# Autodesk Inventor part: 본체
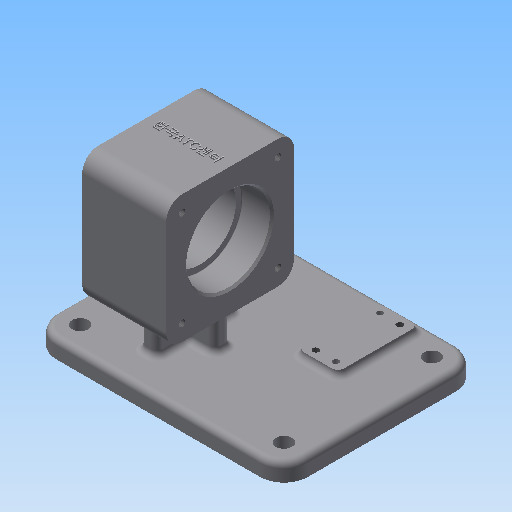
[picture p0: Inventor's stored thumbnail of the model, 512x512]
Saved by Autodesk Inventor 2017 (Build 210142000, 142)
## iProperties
Created: 2019-09
Part Number: 본체
Material: 알루미늄 6061
Document SubType Name: Modeling
Designer: mduedu
Density: 2.71 g/cm^3
Mass: 636.364 g
Surface Area: 520.125 cm^2
Volume: 234.821 cm^3
Appearance: 기본값
Author: mduedu
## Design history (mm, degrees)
sketch "스케치1"
  geometry: L1 (42, -62)-(-84, -62); L2 (-84, -62)-(-84, 36); L3 (-84, 36)-(42, 36); L4 (42, 36)-(42, -62); 1 further point
  constraints: 8 end point, 2 parallel, 1 horizontal, 1 perpendicular
  dimensions: "d0" = 36 distance from line of L3 point (0, 0); "d1" = 98 distance of L1.end L2.end; "d2" = 42 distance from line of L4 point (0, 0); "d3" = 126 distance of L2.end L3.end
extrude "돌출1" new body sketch "스케치1" distance "d4" = 9; taper "d5" = 0 deg
sketch "스케치2"
  geometry: L1 (0, -62)-(0, 36) reference; L2 (27, -32)-(91, -32); L3 (91, -32)-(91, 32); L4 (91, 32)-(27, 32); L5 (27, 32)-(27, -32); L6 (27, -32)-(91, 32); L7 (91, -32)-(27, 32); 3 further points
  constraints: 12 end point, 3 midpoint, 2 parallel, 1 horizontal, 1 horizontal alignment, 1 perpendicular
  dimensions: "d87" = 64 distance of L4.end L3.end; "d88" = 64 distance of L3.end L2.end; "d89" = 59 distance from line of point (59, 0) L1
extrude "돌출2" join sketch "스케치2" stored distance "d8" = 42; taper "d9" = 0 deg
sketch "스케치3"
  geometry: L1 (-17, 4)-(17, 4); L2 (17, 4)-(17, -4); L3 (17, -4)-(-17, -4); L4 (-17, -4)-(-17, 4); L5 (-4, 20)-(4, 20); L6 (4, 20)-(4, -20); L7 (4, -20)-(-4, -20); L8 (-4, -20)-(-4, 20); 5 further points
  constraints: 16 end point, 4 midpoint, 4 parallel, 2 horizontal, 2 horizontal alignment, 2 perpendicular, 2 vertical alignment
  dimensions: "d10" = 8 distance of L5.start L5.end; "d12" = 8 distance of L1.end L2.end; "d13" = 34 distance of L2.end L3.end; "d14" = 40 distance of L5.end L6.end
extrude "돌출3" join sketch "스케치3" stored distance "d15" = 42; taper "d16" = 0 deg
sketch "스케치4"
  geometry: L1 (-32, 91)-(-32, 27) reference; L2 (32, 91)-(-32, 91) reference; L3 (32, 27)-(32, 91) reference; L4 (-32, 27)-(32, 27) reference; C1 r 21 at (0, 59); 3 further points
  constraints: 2 midpoint, 1 centre point, 1 horizontal alignment, 1 vertical alignment
  dimensions: "d17" = 42 diameter of C1
extrude "돌출4" cut sketch "스케치4" distance "d18" = 15; taper "d19" = 0 deg
hole "구멍1" diameter "d22" = 36; stored, may be unused: countersink angle "d26" = 90 deg, drill point angle "d28" = 118 deg; dims "d20" = 10, "d21" = 10, "d23" = 6, "d24" = 4, "d25" = 2, "d27" = 8
fillet "모깎기1" dims "d29" = 0.3
chamfer "모따기1" distance "d30" = 1; stored, may be unused: second distance "d31" = 2, angle "d32" = 45 deg
fillet "모깎기9" dims "d90" = 8
sketch "스케치11"
  geometry: L1 (-24, 27)-(24, 27) reference; L2 (32, 35)-(32, 83) reference; L3 (24, 91)-(-24, 91) reference; L4 (-32, 83)-(-32, 35) reference; C1 r 22 at (0, 59) reference; A1 r 8 centre (-24, 35) between (-32, 35) and (-24, 27) reference; A2 r 8 centre (24, 35) between (24, 27) and (32, 35) reference; A3 r 8 centre (24, 83) between (32, 83) and (24, 91) reference; A4 r 8 centre (-24, 83) between (-24, 91) and (-32, 83) reference; 5 further points
  constraints: 4 coincident
hole "구멍6" sketch "스케치11" at (-24, 83), (24, 83), (24, 35), (-24, 35) diameter "d91" = 3.242; stored, may be unused: countersink angle "d95" = 90 deg, drill point angle "d97" = 118 deg; dims "d92" = 8, "d93" = 4, "d94" = 2, "d96" = 10
fillet "모깎기2" dims "d44" = 12
sketch "스케치6"
  geometry: L1 (-42, 50)-(-42, -24) reference; L2 (-30, -36)-(72, -36) reference; L3 (84, -24)-(84, 50) reference; L4 (72, 62)-(-30, 62) reference; L5 (17, 4)-(17, -4) reference; L6 (17, -4)-(4, -4) reference; L7 (4, -4)-(4, -20) reference; L8 (4, -20)-(-4, -20) reference; L9 (-4, -20)-(-4, -4) reference; L10 (-4, -4)-(-17, -4) reference; L11 (-17, -4)-(-17, 4) reference; L12 (-17, 4)-(-4, 4) reference; L13 (-4, 4)-(-4, 20) reference; L14 (-4, 20)-(4, 20) reference; L15 (4, 20)-(4, 4) reference; L16 (4, 4)-(17, 4) reference; A1 r 12 centre (-30, 50) between (-30, 62) and (-42, 50) reference; A2 r 12 centre (-30, -24) between (-42, -24) and (-30, -36) reference; A3 r 12 centre (72, -24) between (72, -36) and (84, -24) reference; A4 r 12 centre (72, 50) between (84, 50) and (72, 62) reference; 5 further points
  constraints: 4 coincident
hole "구멍3" sketch "스케치6" at (-30, 50), (72, 50), (72, -24), (-30, -24) diameter "d45" = 8; stored, may be unused: countersink angle "d49" = 90 deg, drill point angle "d51" = 118 deg; dims "d46" = 8, "d47" = 4, "d48" = 2, "d50" = 10
sketch "스케치7"
  geometry: L1 (38, 57)-(58, 57); L2 (58, 57)-(58, 17); L3 (58, 17)-(38, 17); L4 (38, 17)-(38, 57); L5 (72, 62)-(-30, 62) reference; 3 further points
  constraints: 8 end point, 2 midpoint, 2 parallel, 1 horizontal, 1 perpendicular
  dimensions: "d52" = 48 horizontal distance of point (48, 57) point (0, 0); "d53" = 20 distance of L1.start L1.end; "d54" = 40 distance of L1.end L2.end; "d55" = 25 distance from line of point (38, 37) L5
extrude "돌출5" join sketch "스케치7" distance "d56" = 3; taper "d57" = 0 deg
fillet "모깎기3" dims "d58" = 3
fillet "모깎기4" dims "d59" = 3
fillet "모깎기5" dims "d60" = 3
fillet "모깎기6" dims "d61" = 3
fillet "모깎기7" dims "d62" = 3
fillet "모깎기8" dims "d63" = 3
sketch "스케치8"
  geometry: L1 (72, 62)-(58.317, 62) reference; L2 (84, -24)-(84, 50) reference; C1 r 1.5 at (43, 53); C2 r 1.5 at (53, 21); 1 further point
  constraints: 2 centre point, 1 equal radius
  dimensions: "d64" = 3 diameter of C1; "d65" = 9 distance from line of C1.centre L1; "d66" = 32 vertical distance of C2.centre C1.centre; "d67" = 10 horizontal distance of C2.centre C1.centre; "d68" = 31 distance from line of L2 C2.centre
hole "구멍4" sketch "스케치8" at (43, 53), (53, 21) diameter "d69" = 3; stored, may be unused: countersink angle "d73" = 90 deg, drill point angle "d75" = 118 deg; dims "d70" = 8, "d71" = 4, "d72" = 2, "d74" = 6
sketch "스케치9"
  geometry: C1 r 1.5 at (43, 53) reference; C2 r 1.5 at (53, 21) reference; 3 further points
  constraints: 2 horizontal alignment, 2 vertical alignment
hole "구멍5" sketch "스케치9" at (53, 53), (43, 21) diameter "d76" = 3.242; stored, may be unused: countersink angle "d80" = 90 deg, drill point angle "d82" = 118 deg; dims "d77" = 6, "d78" = 4, "d79" = 2, "d81" = 8
sketch "스케치10"
  geometry: 2 further points
  constraints: 1 coincident, 1 other
feature "엠보싱1" sketch "스케치10" dims "d0" = 36, "d1" = 98, "d2" = 42, "d3" = 126, "d12" = 8, "d13" = 34, "d85" = 0.5, "d86" = 0
node "솔리드1"
mirror "대칭1"
mirror "대칭2"
node "투영된 루프1"
node "투영된 루프2"
